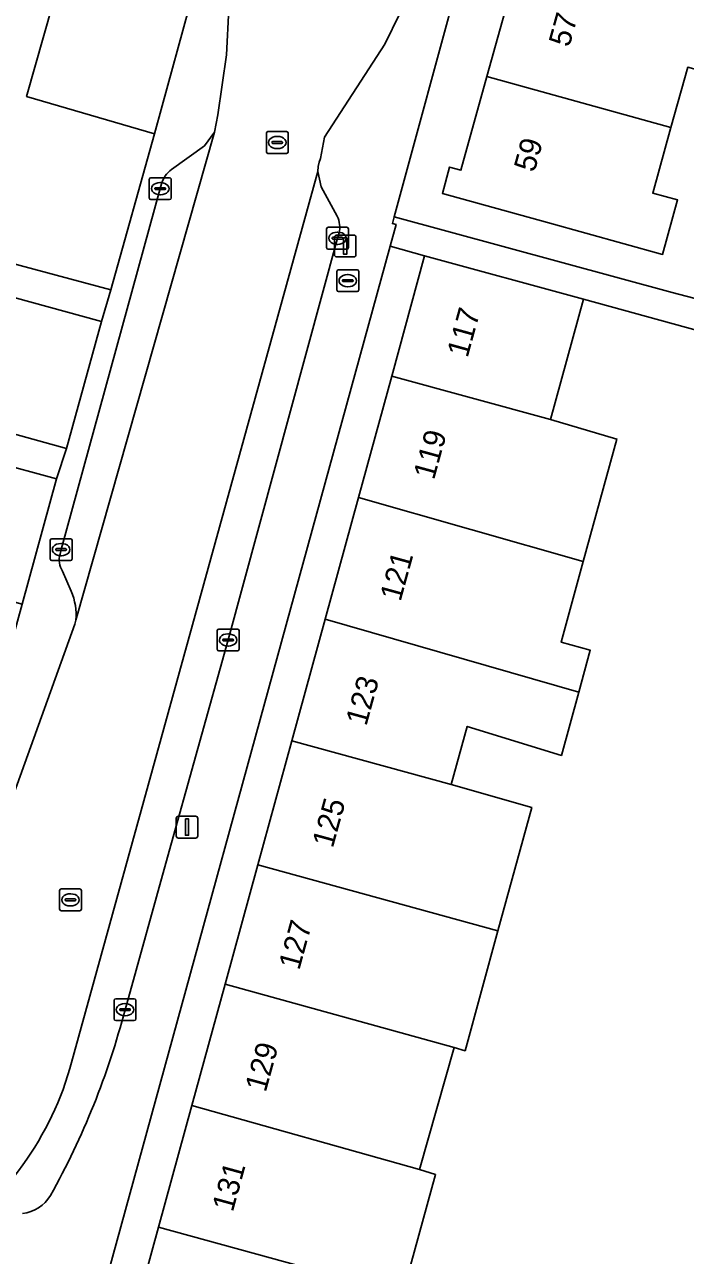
# Model space of a CAD drawing. Extents: x 159817 to 160765, y 380688 to 381638.
# Drawn here: x 160248 to 160278.3, y 381110.3 to 381166.7 of the extents above; entities that cross this region are included whole.
import ezdxf

# ---------------------------------------------------------------- set-up
doc = ezdxf.new("R2010")
doc.units = 0
for name, color, linetype in [('IMGEO_Brandkraan', 7, 'Continuous'), ('IMGEO_Erf', 7, 'Continuous'), ('IMGEO_Groenvoorziening', 7, 'Continuous'), ('IMGEO_Kolk', 7, 'Continuous'), ('IMGEO_Lichtmast', 7, 'Continuous'), ('IMGEO_Pand', 7, 'Continuous'), ('IMGEO_Pand_nummerreeks', 7, 'Continuous'), ('IMGEO_Parkeervlak_open', 7, 'Continuous'), ('IMGEO_Rijbaan_lokaal_open', 7, 'Continuous'), ('IMGEO_Rioolput', 7, 'Continuous'), ('IMGEO_Voetpad_open', 7, 'Continuous')]:
    doc.layers.add(name, color=color, linetype=linetype)

msp = doc.modelspace()

# ---------------------------------------------------------------- linework, layer by layer
at = {"layer": 'IMGEO_Brandkraan'}
for p, q in [((160262.331, 381154.508), (160262.331, 381155.36)), ((160262.406, 381155.434), (160263.258, 381155.434)), ((160263.332, 381155.36), (160263.332, 381154.508)), ((160262.59, 381154.928), (160262.59, 381154.94)), ((160263.028, 381154.891), (160262.63, 381154.891)), ((160262.633, 381154.977), (160263.031, 381154.977)), ((160262.819, 381155.214), (160262.844, 381155.214)), ((160263.074, 381154.94), (160263.074, 381154.928)), ((160263.258, 381154.434), (160262.406, 381154.434)), ((160262.842, 381154.654), (160262.817, 381154.654))]:
    msp.add_line(p, q, dxfattribs=at)
for points in [[(160262.331, 381154.508), (160262.331, 381155.36)], [(160262.406, 381155.434), (160263.258, 381155.434)], [(160263.332, 381155.36), (160263.332, 381154.508)], [(160263.258, 381154.434), (160262.406, 381154.434)]]:
    msp.add_lwpolyline(points, dxfattribs=at)
for centre, radius, start, end in [((160262.408, 381155.358), 0.0765, 91.552, 178.448), ((160262.408, 381155.358), 0.0765, 91.552, 178.448), ((160263.256, 381155.358), 0.0765, 1.552, 88.448), ((160263.256, 381155.358), 0.0765, 1.552, 88.448), ((160262.63, 381154.937), 0.0403, 85.8775, 175.7526), ((160262.627, 381154.927), 0.0366, 178.938, 274.7102), ((160263.031, 381154.934), 0.043, 264.8664, 352.4533), ((160263.035, 381154.939), 0.0386, 1.7309, 96.639), ((160262.408, 381154.51), 0.0765, 181.552, 268.448), ((160262.408, 381154.51), 0.0765, 181.552, 268.448), ((160263.256, 381154.51), 0.0765, 271.552, 358.448), ((160263.256, 381154.51), 0.0765, 271.552, 358.448)]:
    msp.add_arc(centre, radius, start, end, dxfattribs=at)
for centre, major_axis, ratio, start_param, end_param in [((160262.818, 381154.934), (-0.387, 0.002), 0.722429, 4.712389, 7.853982), ((160262.843, 381154.934), (-0.39, 0.002), 0.717154, 1.570796, 4.712389)]:
    msp.add_ellipse(centre, major_axis=major_axis, ratio=ratio, start_param=start_param, end_param=end_param, dxfattribs=at)
at = {"layer": 'IMGEO_Erf'}
for points in [[(160274.082, 381191.318), (160264.96, 381157.861), (160277.691, 381154.39), (160284.311, 381152.663), (160286.809, 381151.98), (160287.341, 381151.835), (160287.458, 381152.277), (160287.711, 381153.232), (160289.094, 381158.456), (160289.63, 381160.481), (160289.745, 381160.917), (160287.909, 381161.403), (160288.668, 381164.276), (160288.717, 381164.46), (160290.557, 381163.973), (160292.46, 381170.81)], [(160278.407, 381164.716), (160277.639, 381161.95), (160276.806, 381158.949), (160277.946, 381158.632), (160277.252, 381156.136), (160271.983, 381157.599), (160267.165, 381158.936), (160267.499, 381160.14), (160268.017, 381159.996), (160269.208, 381164.286), (160270.321, 381168.294)], [(160288.399, 381150.03), (160273.629, 381154.081), (160272.114, 381148.568), (160275.165, 381147.678), (160273.624, 381142.072), (160272.606, 381138.37), (160273.942, 381138.003), (160273.415, 381136.085), (160272.617, 381133.182), (160268.306, 381134.517), (160267.572, 381131.846), (160271.264, 381130.794), (160269.713, 381125.152), (160268.203, 381119.657), (160267.706, 381119.799), (160266.114, 381114.212), (160266.858, 381113.99), (160265.329, 381108.426)]]:
    msp.add_lwpolyline(points, dxfattribs=at)
msp.add_lwpolyline([(160261.794, 381139.428), (160263.319, 381144.997), (160264.844, 381150.565), (160266.354, 381156.08), (160264.775, 381156.514), (160249.46, 381100.752), (160251.081, 381100.307), (160252.639, 381105.997), (160254.167, 381111.576), (160255.692, 381117.147), (160257.217, 381122.713), (160258.712, 381128.174), (160260.267, 381133.853)], close=True, dxfattribs=at)
at = {"layer": 'IMGEO_Groenvoorziening'}
msp.add_lwpolyline([(160238.444, 381212.887), (160236.175, 381203.453), (160233.837, 381193.057), (160231.978, 381181.186), (160231.145, 381175.866), (160230.799, 381173.658), (160230.208, 381169.457), (160229.089, 381160.661), (160251.97, 381154.51), (160253.975, 381161.663), (160248.118, 381163.38), (160249.697, 381168.977), (160255.528, 381167.35), (160255.658, 381167.83), (160264.718, 381201.384), (160266.993, 381208.842)], dxfattribs=at)
for points in [[(160254.334, 381162.942), (160255.528, 381167.35), (160249.697, 381168.977), (160248.118, 381163.38), (160253.975, 381161.663)], [(160251.548, 381153.059), (160245.913, 381154.613), (160244.309, 381148.797), (160249.944, 381147.243)], [(160249.487, 381145.85), (160243.64, 381147.451), (160242.068, 381141.709), (160247.915, 381140.108)]]:
    msp.add_lwpolyline(points, close=True, dxfattribs=at)
at = {"layer": 'IMGEO_Kolk'}
for p, q in [((160253.74, 381158.725), (160253.74, 381159.577)), ((160253.815, 381159.651), (160254.667, 381159.651)), ((160254.228, 381159.431), (160254.253, 381159.431)), ((160254.741, 381159.577), (160254.741, 381158.725)), ((160253.999, 381159.145), (160253.999, 381159.157)), ((160254.437, 381159.108), (160254.039, 381159.108)), ((160254.042, 381159.194), (160254.44, 381159.194)), ((160254.251, 381158.871), (160254.226, 381158.871)), ((160254.483, 381159.157), (160254.483, 381159.145)), ((160254.667, 381158.651), (160253.815, 381158.651)), ((160261.861, 381156.453), (160261.861, 381157.305)), ((160261.936, 381157.379), (160262.788, 381157.379)), ((160262.349, 381157.159), (160262.374, 381157.159)), ((160262.862, 381157.305), (160262.862, 381156.453)), ((160262.12, 381156.873), (160262.12, 381156.885)), ((160262.558, 381156.836), (160262.16, 381156.836)), ((160262.163, 381156.922), (160262.561, 381156.922)), ((160262.372, 381156.599), (160262.347, 381156.599)), ((160262.604, 381156.885), (160262.604, 381156.873)), ((160262.788, 381156.379), (160261.936, 381156.379)), ((160249.198, 381142.189), (160249.198, 381143.041)), ((160249.273, 381143.115), (160250.125, 381143.115)), ((160250.199, 381143.041), (160250.199, 381142.189)), ((160249.457, 381142.609), (160249.457, 381142.621)), ((160249.895, 381142.572), (160249.497, 381142.572)), ((160249.5, 381142.658), (160249.898, 381142.658)), ((160249.686, 381142.895), (160249.711, 381142.895)), ((160249.941, 381142.621), (160249.941, 381142.609)), ((160250.125, 381142.115), (160249.273, 381142.115)), ((160249.709, 381142.335), (160249.684, 381142.335)), ((160256.85, 381138.049), (160256.85, 381138.901)), ((160256.925, 381138.975), (160257.777, 381138.975)), ((160257.109, 381138.469), (160257.109, 381138.481)), ((160257.547, 381138.432), (160257.149, 381138.432)), ((160257.152, 381138.518), (160257.55, 381138.518)), ((160257.338, 381138.755), (160257.363, 381138.755)), ((160257.593, 381138.481), (160257.593, 381138.469)), ((160257.851, 381138.901), (160257.851, 381138.049)), ((160257.777, 381137.975), (160256.925, 381137.975)), ((160257.361, 381138.195), (160257.336, 381138.195)), ((160252.126, 381121.111), (160252.126, 381121.963)), ((160252.201, 381122.037), (160253.053, 381122.037)), ((160252.385, 381121.531), (160252.385, 381121.543)), ((160252.428, 381121.58), (160252.826, 381121.58)), ((160252.614, 381121.817), (160252.639, 381121.817)), ((160252.869, 381121.543), (160252.869, 381121.531)), ((160253.127, 381121.963), (160253.127, 381121.111)), ((160253.053, 381121.037), (160252.201, 381121.037)), ((160252.823, 381121.494), (160252.425, 381121.494)), ((160252.637, 381121.257), (160252.612, 381121.257))]:
    msp.add_line(p, q, dxfattribs=at)
for points in [[(160253.74, 381158.725), (160253.74, 381159.577)], [(160253.815, 381159.651), (160254.667, 381159.651)], [(160254.741, 381159.577), (160254.741, 381158.725)], [(160254.667, 381158.651), (160253.815, 381158.651)], [(160261.861, 381156.453), (160261.861, 381157.305)], [(160261.936, 381157.379), (160262.788, 381157.379)], [(160262.862, 381157.305), (160262.862, 381156.453)], [(160262.788, 381156.379), (160261.936, 381156.379)], [(160249.198, 381142.189), (160249.198, 381143.041)], [(160249.273, 381143.115), (160250.125, 381143.115)], [(160250.199, 381143.041), (160250.199, 381142.189)], [(160250.125, 381142.115), (160249.273, 381142.115)], [(160256.85, 381138.049), (160256.85, 381138.901)], [(160256.925, 381138.975), (160257.777, 381138.975)], [(160257.851, 381138.901), (160257.851, 381138.049)], [(160257.777, 381137.975), (160256.925, 381137.975)], [(160252.126, 381121.111), (160252.126, 381121.963)], [(160252.201, 381122.037), (160253.053, 381122.037)], [(160253.127, 381121.963), (160253.127, 381121.111)], [(160253.053, 381121.037), (160252.201, 381121.037)]]:
    msp.add_lwpolyline(points, dxfattribs=at)
for centre, radius, start, end in [((160253.817, 381159.575), 0.0765, 91.552, 178.448), ((160253.817, 381159.575), 0.0765, 91.552, 178.448), ((160254.665, 381159.575), 0.0765, 1.552, 88.448), ((160254.665, 381159.575), 0.0765, 1.552, 88.448), ((160253.817, 381158.727), 0.0765, 181.552, 268.448), ((160253.817, 381158.727), 0.0765, 181.552, 268.448), ((160254.039, 381159.154), 0.0403, 85.8775, 175.7526), ((160254.036, 381159.144), 0.0366, 178.938, 274.7102), ((160254.44, 381159.151), 0.043, 264.8664, 352.4533), ((160254.444, 381159.156), 0.0386, 1.7309, 96.639), ((160254.665, 381158.727), 0.0765, 271.552, 358.448), ((160254.665, 381158.727), 0.0765, 271.552, 358.448), ((160261.938, 381157.303), 0.0765, 91.552, 178.448), ((160261.938, 381157.303), 0.0765, 91.552, 178.448), ((160262.786, 381157.303), 0.0765, 1.552, 88.448), ((160262.786, 381157.303), 0.0765, 1.552, 88.448), ((160262.16, 381156.882), 0.0403, 85.8775, 175.7526), ((160262.157, 381156.872), 0.0366, 178.938, 274.7102), ((160262.561, 381156.879), 0.043, 264.8664, 352.4533), ((160262.565, 381156.884), 0.0386, 1.7309, 96.639), ((160261.938, 381156.455), 0.0765, 181.552, 268.448), ((160261.938, 381156.455), 0.0765, 181.552, 268.448), ((160262.786, 381156.455), 0.0765, 271.552, 358.448), ((160262.786, 381156.455), 0.0765, 271.552, 358.448), ((160249.275, 381143.039), 0.0765, 91.552, 178.448), ((160249.275, 381143.039), 0.0765, 91.552, 178.448), ((160250.123, 381143.039), 0.0765, 1.552, 88.448), ((160250.123, 381143.039), 0.0765, 1.552, 88.448), ((160249.497, 381142.618), 0.0403, 85.8775, 175.7526), ((160249.494, 381142.608), 0.0366, 178.938, 274.7102), ((160249.898, 381142.615), 0.043, 264.8664, 352.4533), ((160249.902, 381142.62), 0.0386, 1.7309, 96.639), ((160249.275, 381142.191), 0.0765, 181.552, 268.448), ((160249.275, 381142.191), 0.0765, 181.552, 268.448), ((160250.123, 381142.191), 0.0765, 271.552, 358.448), ((160250.123, 381142.191), 0.0765, 271.552, 358.448), ((160256.927, 381138.899), 0.0765, 91.552, 178.448), ((160256.927, 381138.899), 0.0765, 91.552, 178.448), ((160257.149, 381138.478), 0.0403, 85.8775, 175.7526), ((160257.146, 381138.468), 0.0366, 178.938, 274.7102), ((160257.55, 381138.475), 0.043, 264.8664, 352.4533), ((160257.554, 381138.48), 0.0386, 1.7309, 96.639), ((160257.775, 381138.899), 0.0765, 1.552, 88.448), ((160257.775, 381138.899), 0.0765, 1.552, 88.448), ((160256.927, 381138.051), 0.0765, 181.552, 268.448), ((160256.927, 381138.051), 0.0765, 181.552, 268.448), ((160257.775, 381138.051), 0.0765, 271.552, 358.448), ((160257.775, 381138.051), 0.0765, 271.552, 358.448), ((160252.203, 381121.961), 0.0765, 91.552, 178.448), ((160252.203, 381121.961), 0.0765, 91.552, 178.448), ((160252.425, 381121.54), 0.0403, 85.8775, 175.7526), ((160252.422, 381121.53), 0.0366, 178.938, 274.7102), ((160252.826, 381121.537), 0.043, 264.8664, 352.4533), ((160252.83, 381121.542), 0.0386, 1.7309, 96.639), ((160253.051, 381121.961), 0.0765, 1.552, 88.448), ((160253.051, 381121.961), 0.0765, 1.552, 88.448), ((160252.203, 381121.113), 0.0765, 181.552, 268.448), ((160252.203, 381121.113), 0.0765, 181.552, 268.448), ((160253.051, 381121.113), 0.0765, 271.552, 358.448), ((160253.051, 381121.113), 0.0765, 271.552, 358.448)]:
    msp.add_arc(centre, radius, start, end, dxfattribs=at)
for centre, major_axis, ratio, start_param, end_param in [((160254.227, 381159.151), (-0.387, 0.002), 0.722429, 4.712389, 7.853982), ((160254.252, 381159.151), (-0.39, 0.002), 0.717154, 1.570796, 4.712389), ((160262.348, 381156.879), (-0.387, 0.002), 0.722429, 4.712389, 7.853982), ((160262.373, 381156.879), (-0.39, 0.002), 0.717154, 1.570796, 4.712389), ((160249.685, 381142.615), (-0.387, 0.002), 0.722429, 4.712389, 7.853982), ((160249.71, 381142.615), (-0.39, 0.002), 0.717154, 1.570796, 4.712389), ((160257.337, 381138.475), (-0.387, 0.002), 0.722429, 4.712389, 7.853982), ((160257.362, 381138.475), (-0.39, 0.002), 0.717154, 1.570796, 4.712389), ((160252.613, 381121.537), (-0.387, 0.002), 0.722429, 4.712389, 7.853982), ((160252.638, 381121.537), (-0.39, 0.002), 0.717154, 1.570796, 4.712389)]:
    msp.add_ellipse(centre, major_axis=major_axis, ratio=ratio, start_param=start_param, end_param=end_param, dxfattribs=at)
at = {"layer": 'IMGEO_Lichtmast'}
for p, q in [((160262.318, 381157.021), (160263.108, 381157.021)), ((160263.108, 381157.021), (160262.318, 381157.021)), ((160262.218, 381156.121), (160262.218, 381156.921)), ((160262.218, 381156.921), (160262.218, 381156.121)), ((160263.208, 381156.921), (160263.208, 381156.121)), ((160263.208, 381156.121), (160263.208, 381156.921)), ((160263.108, 381156.021), (160262.318, 381156.021)), ((160262.318, 381156.021), (160263.108, 381156.021)), ((160254.972, 381129.502), (160254.972, 381130.302)), ((160254.972, 381130.302), (160254.972, 381129.502)), ((160255.072, 381130.402), (160255.862, 381130.402)), ((160255.862, 381130.402), (160255.072, 381130.402)), ((160255.962, 381130.302), (160255.962, 381129.502)), ((160255.962, 381129.502), (160255.962, 381130.302)), ((160255.862, 381129.402), (160255.072, 381129.402)), ((160255.072, 381129.402), (160255.862, 381129.402))]:
    msp.add_line(p, q, dxfattribs=at)
for points in [[(160262.638, 381156.896), (160262.788, 381156.896), (160262.788, 381156.146), (160262.638, 381156.146), (160262.638, 381156.896)], [(160255.392, 381130.277), (160255.542, 381130.277), (160255.542, 381129.527), (160255.392, 381129.527), (160255.392, 381130.277)]]:
    msp.add_lwpolyline(points, dxfattribs=at)
for centre, start, end in [((160262.318, 381156.921), 90, 180), ((160262.318, 381156.921), 90, 180), ((160263.108, 381156.921), 0, 90), ((160263.108, 381156.921), 360, 90), ((160262.318, 381156.121), 180, 270), ((160262.318, 381156.121), 180, 270), ((160263.108, 381156.121), 270, 0), ((160263.108, 381156.121), 270, 0), ((160255.072, 381130.302), 90, 180), ((160255.072, 381130.302), 90, 180), ((160255.862, 381130.302), 0, 90), ((160255.862, 381130.302), 360, 90), ((160255.072, 381129.502), 180, 270), ((160255.072, 381129.502), 180, 270), ((160255.862, 381129.502), 270, 0), ((160255.862, 381129.502), 270, 0)]:
    msp.add_arc(centre, 0.1, start, end, dxfattribs=at)
at = {"layer": 'IMGEO_Pand'}
for points in [[(160269.208, 381164.286), (160277.639, 381161.95), (160278.407, 381164.716), (160279.539, 381164.402), (160280.213, 381166.829), (160270.154, 381169.692), (160269.806, 381168.437), (160270.321, 381168.294)], [(160269.208, 381164.286), (160268.017, 381159.996), (160267.499, 381160.14), (160267.165, 381158.936), (160271.983, 381157.599), (160277.252, 381156.136), (160277.946, 381158.632), (160276.806, 381158.949), (160277.639, 381161.95)], [(160272.114, 381148.568), (160273.629, 381154.081), (160266.354, 381156.08), (160264.844, 381150.565)], [(160272.114, 381148.568), (160264.844, 381150.565), (160263.319, 381144.997), (160273.624, 381142.072), (160275.165, 381147.678)], [(160263.319, 381144.997), (160261.794, 381139.428), (160273.415, 381136.085), (160273.942, 381138.003), (160272.606, 381138.37), (160273.624, 381142.072)], [(160260.267, 381133.853), (160267.572, 381131.846), (160268.306, 381134.517), (160272.617, 381133.182), (160273.415, 381136.085), (160261.794, 381139.428)], [(160260.267, 381133.853), (160258.712, 381128.174), (160269.713, 381125.152), (160271.264, 381130.794), (160267.572, 381131.846)], [(160257.217, 381122.713), (160267.706, 381119.799), (160268.203, 381119.657), (160269.713, 381125.152), (160258.712, 381128.174)], [(160257.217, 381122.713), (160255.692, 381117.147), (160266.114, 381114.212), (160267.706, 381119.799)], [(160254.167, 381111.576), (160261.452, 381109.574), (160265.329, 381108.426), (160266.858, 381113.99), (160266.114, 381114.212), (160255.692, 381117.147)], [(160254.167, 381111.576), (160252.639, 381105.997), (160259.919, 381103.997), (160261.452, 381109.574)]]:
    msp.add_lwpolyline(points, close=True, dxfattribs=at)
at = {"layer": 'IMGEO_Parkeervlak_open'}
for points in [[(160250.376, 381139.385), (160256.732, 381161.736), (160256.268, 381161.111), (160254.763, 381160.021)], [(160261.458, 381159.935), (160250.096, 381118.836), (160249.786, 381117.875)], [(160262.349, 381157.883), (160261.617, 381159.24), (160261.458, 381159.935)], [(160254.295, 381159.37), (160254.242, 381159.151), (160249.7, 381142.614), (160249.649, 381142.406)], [(160252.627, 381121.537), (160254.566, 381128.524), (160257.35, 381138.475), (160262.361, 381156.88), (160262.439, 381157.121)], [(160249.76, 381141.627), (160250.162, 381140.709)]]:
    msp.add_lwpolyline(points, dxfattribs=at)
for centre, radius, start, end in [((160255.397, 381159.072), 1.141, 123.7264, 164.8494), ((160261.254, 381157.367), 1.211, 348.2616, 25.2104), ((160250.595, 381142.143), 0.981, 164.4775, 211.7415), ((160247.655, 381139.625), 2.731, 354.9686, 23.3942), ((160217.914, 381130.528), 35.858, 330.7784, 345.4796), ((160235.937, 381123.049), 14.784, 319.2217, 339.5148), ((160247.726, 381113.92), 1.734, 276.9304, 328.7943)]:
    msp.add_arc(centre, radius, start, end, dxfattribs=at)
at = {"layer": 'IMGEO_Rijbaan_lokaal_open'}
for points in [[(160249.786, 381117.875), (160250.096, 381118.836), (160261.458, 381159.935), (160261.475, 381160.166), (160261.515, 381160.362), (160261.575, 381160.539), (160261.771, 381161.504), (160264.535, 381165.771), (160265.212, 381167.176), (160265.672, 381168.841), (160266.042, 381170.167), (160266.18, 381172.344), (160266.032, 381176.002), (160266.094, 381176.937), (160266.359, 381177.913), (160270.433, 381192.916)], [(160258.337, 381172.644), (160257.87, 381170.934), (160257.484, 381169.51), (160257.281, 381165.283), (160256.885, 381162.535), (160256.732, 381161.736), (160250.376, 381139.385), (160250.325, 381139.205), (160244.747, 381123.749)]]:
    msp.add_lwpolyline(points, dxfattribs=at)
msp.add_arc((160235.937, 381123.049), 14.784, 319.2217, 339.5148, dxfattribs=at)
at = {"layer": 'IMGEO_Rioolput'}
for p, q in [((160259.101, 381160.839), (160259.101, 381161.691)), ((160259.176, 381161.765), (160260.028, 381161.765)), ((160259.589, 381161.545), (160259.614, 381161.545)), ((160260.102, 381161.691), (160260.102, 381160.839)), ((160259.36, 381161.259), (160259.36, 381161.271)), ((160259.798, 381161.222), (160259.4, 381161.222)), ((160259.403, 381161.308), (160259.801, 381161.308)), ((160259.612, 381160.985), (160259.587, 381160.985)), ((160259.844, 381161.271), (160259.844, 381161.259)), ((160260.028, 381160.765), (160259.176, 381160.765)), ((160249.628, 381126.141), (160249.628, 381126.993)), ((160249.703, 381127.067), (160250.555, 381127.067)), ((160249.887, 381126.561), (160249.887, 381126.573)), ((160249.93, 381126.61), (160250.328, 381126.61)), ((160250.116, 381126.847), (160250.141, 381126.847)), ((160250.371, 381126.573), (160250.371, 381126.561)), ((160250.629, 381126.993), (160250.629, 381126.141)), ((160250.555, 381126.067), (160249.703, 381126.067)), ((160250.325, 381126.524), (160249.927, 381126.524)), ((160250.139, 381126.287), (160250.114, 381126.287))]:
    msp.add_line(p, q, dxfattribs=at)
for points in [[(160259.101, 381160.839), (160259.101, 381161.691)], [(160259.176, 381161.765), (160260.028, 381161.765)], [(160260.102, 381161.691), (160260.102, 381160.839)], [(160260.028, 381160.765), (160259.176, 381160.765)], [(160249.628, 381126.141), (160249.628, 381126.993)], [(160249.703, 381127.067), (160250.555, 381127.067)], [(160250.629, 381126.993), (160250.629, 381126.141)], [(160250.555, 381126.067), (160249.703, 381126.067)]]:
    msp.add_lwpolyline(points, dxfattribs=at)
for centre, radius, start, end in [((160259.178, 381161.689), 0.0765, 91.552, 178.448), ((160259.178, 381161.689), 0.0765, 91.552, 178.448), ((160260.026, 381161.689), 0.0765, 1.552, 88.448), ((160260.026, 381161.689), 0.0765, 1.552, 88.448), ((160259.4, 381161.268), 0.0403, 85.8775, 175.7526), ((160259.397, 381161.258), 0.0366, 178.938, 274.7102), ((160259.801, 381161.265), 0.043, 264.8664, 352.4533), ((160259.805, 381161.27), 0.0386, 1.7309, 96.639), ((160259.178, 381160.841), 0.0765, 181.552, 268.448), ((160259.178, 381160.841), 0.0765, 181.552, 268.448), ((160260.026, 381160.841), 0.0765, 271.552, 358.448), ((160260.026, 381160.841), 0.0765, 271.552, 358.448), ((160249.705, 381126.991), 0.0765, 91.552, 178.448), ((160249.705, 381126.991), 0.0765, 91.552, 178.448), ((160249.927, 381126.57), 0.0403, 85.8775, 175.7526), ((160250.332, 381126.572), 0.0386, 1.7309, 96.639), ((160250.553, 381126.991), 0.0765, 1.552, 88.448), ((160250.553, 381126.991), 0.0765, 1.552, 88.448), ((160249.705, 381126.143), 0.0765, 181.552, 268.448), ((160249.705, 381126.143), 0.0765, 181.552, 268.448), ((160249.924, 381126.56), 0.0366, 178.938, 274.7102), ((160250.328, 381126.567), 0.043, 264.8664, 352.4533), ((160250.553, 381126.143), 0.0765, 271.552, 358.448), ((160250.553, 381126.143), 0.0765, 271.552, 358.448)]:
    msp.add_arc(centre, radius, start, end, dxfattribs=at)
for centre, major_axis, ratio, start_param, end_param in [((160259.588, 381161.265), (-0.387, 0.002), 0.722429, 4.712389, 7.853982), ((160259.613, 381161.265), (-0.39, 0.002), 0.717154, 1.570796, 4.712389), ((160250.115, 381126.567), (-0.387, 0.002), 0.722429, 4.712389, 7.853982), ((160250.14, 381126.567), (-0.39, 0.002), 0.717154, 1.570796, 4.712389)]:
    msp.add_ellipse(centre, major_axis=major_axis, ratio=ratio, start_param=start_param, end_param=end_param, dxfattribs=at)
at = {"layer": 'IMGEO_Voetpad_open'}
for points in [[(160273.86, 381228.53), (160272.472, 381225.02), (160271.906, 381223.588), (160271.359, 381222.034), (160268.762, 381214.643), (160266.993, 381208.842), (160264.718, 381201.384), (160255.658, 381167.83), (160255.528, 381167.35), (160254.334, 381162.942), (160253.975, 381161.663), (160251.97, 381154.51), (160251.548, 381153.059), (160249.944, 381147.243), (160249.487, 381145.85), (160247.915, 381140.108), (160247.058, 381136.994), (160246.977, 381136.698), (160246.121, 381133.645), (160246.041, 381133.358), (160245.124, 381130.087), (160244.977, 381129.563)], [(160237.726, 381100.461), (160243.082, 381099.217), (160244.527, 381098.85), (160248.629, 381097.728), (160249.46, 381100.752), (160264.775, 381156.514), (160265.047, 381157.506), (160264.876, 381157.554), (160264.96, 381157.861), (160274.082, 381191.318)], [(160266.359, 381177.913), (160266.094, 381176.937), (160266.032, 381176.002), (160266.18, 381172.344), (160266.042, 381170.167), (160265.672, 381168.841), (160265.212, 381167.176), (160264.535, 381165.771), (160261.771, 381161.504), (160261.575, 381160.539), (160261.515, 381160.362), (160261.475, 381160.166), (160261.458, 381159.935), (160261.617, 381159.24), (160262.349, 381157.883)], [(160254.763, 381160.021), (160256.268, 381161.111), (160256.732, 381161.736), (160256.885, 381162.535), (160257.281, 381165.283), (160257.484, 381169.51), (160257.87, 381170.934), (160258.337, 381172.644)], [(160249.649, 381142.406), (160249.7, 381142.614), (160254.242, 381159.151), (160254.295, 381159.37)], [(160262.439, 381157.121), (160262.361, 381156.88), (160257.35, 381138.475), (160254.566, 381128.524), (160252.627, 381121.537)], [(160250.162, 381140.709), (160249.76, 381141.627)], [(160244.747, 381123.749), (160250.325, 381139.205), (160250.376, 381139.385)]]:
    msp.add_lwpolyline(points, dxfattribs=at)
for points in [[(160249.944, 381147.243), (160244.309, 381148.797), (160245.913, 381154.613), (160251.548, 381153.059), (160251.97, 381154.51), (160229.089, 381160.661), (160226.774, 381142.455), (160247.058, 381136.994), (160247.915, 381140.108), (160242.068, 381141.709), (160243.64, 381147.451), (160249.487, 381145.85)], [(160287.458, 381152.277), (160287.341, 381151.835), (160286.809, 381151.98), (160284.311, 381152.663), (160277.691, 381154.39), (160264.96, 381157.861), (160264.876, 381157.554), (160265.047, 381157.506), (160264.775, 381156.514), (160266.354, 381156.08), (160273.629, 381154.081), (160288.399, 381150.03), (160292.226, 381148.971), (160293.676, 381148.627), (160297.519, 381147.564), (160312.711, 381143.413), (160314.978, 381142.79), (160319.799, 381141.465), (160322.546, 381140.716), (160322.79, 381141.612), (160323.01, 381141.585), (160323.099, 381141.909), (160323.338, 381142.779)]]:
    msp.add_lwpolyline(points, close=True, dxfattribs=at)
for centre, radius, start, end in [((160255.397, 381159.072), 1.141, 123.7264, 164.8494), ((160261.254, 381157.367), 1.211, 348.2616, 25.2104), ((160250.595, 381142.143), 0.981, 164.4775, 211.7415), ((160247.655, 381139.625), 2.731, 354.9686, 23.3942), ((160217.914, 381130.528), 35.858, 330.7784, 345.4796), ((160247.726, 381113.92), 1.734, 276.9304, 328.7943)]:
    msp.add_arc(centre, radius, start, end, dxfattribs=at)

# ---------------------------------------------------------------- texts
at = {"layer": 'IMGEO_Pand_nummerreeks'}
for s, rotation, p in [('57', 74.4682, (160272.978, 381165.596)), ('59', 74.4823, (160271.385, 381159.865)), ('117', 74.6342, (160268.32, 381151.369)), ('119', 74.6342, (160266.783, 381145.775)), ('121', 74.6342, (160265.25, 381140.202)), ('123', 74.6342, (160263.683, 381134.498)), ('125', 74.6342, (160262.146, 381128.904)), ('127', 74.6342, (160260.609, 381123.311)), ('129', 74.6342, (160259.072, 381117.717)), ('131', 74.6342, (160257.564, 381112.233))]:
    msp.add_text(s, height=1, rotation=rotation, dxfattribs=at).set_placement(p)

doc.saveas('drawing.dxf')
